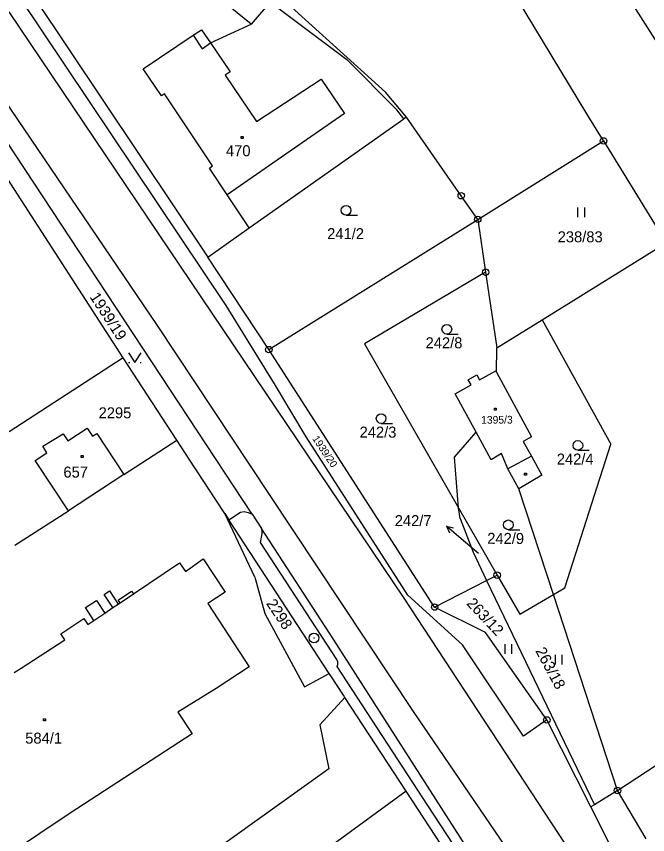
# Model space of a CAD drawing. Extents: x -795483 to -789093, y -1112258 to -1108741.
# Drawn here: x -791519.7 to -791422.1, y -1111421 to -1111294.6 of the extents above; entities that cross this region are included whole.
import ezdxf

# ---------------------------------------------------------------- set-up
doc = ezdxf.new("R2010")
doc.units = 0
for name, color, linetype in [('Komunikace', 7, 'Continuous'), ('Vrstva 1', 7, 'Continuous'), ('Vrstva 14', 7, 'Continuous'), ('Vrstva 15', 7, 'Continuous'), ('Vrstva 16', 7, 'Continuous'), ('Vrstva 2', 7, 'Continuous'), ('Vrstva 23', 7, 'Continuous'), ('Vrstva 25', 7, 'Continuous'), ('Vrstva 28', 7, 'Continuous')]:
    doc.layers.add(name, color=color, linetype=linetype)

msp = doc.modelspace()

# ---------------------------------------------------------------- linework, layer by layer
at = {"layer": 'Komunikace'}
msp.add_line((-791448.27, -1111377.57), (-791450.94, -1111375.27), dxfattribs=at)
at = {"layer": 'Vrstva 1'}
for p, q in [((-791453.88, -1111246.33), (-791418.6, -1111301.97)), ((-791431.53, -1111309.64), (-791464.81, -1111254.53)), ((-791462.64, -1111306.28), (-791491.11, -1111280.51)), ((-791485.12, -1111288.85), (-791468.64, -1111301.26)), ((-791487.25, -1111339.25), (-791519.47, -1111291.13)), ((-791517.06, -1111291.49), (-791490.12, -1111331.77)), ((-791483.4, -1111295.77), (-791487.72, -1111292.28)), ((-791489.68, -1111298.68), (-791483.4, -1111295.77)), ((-791492.38, -1111297.5), (-791491.07, -1111296.63)), ((-791491.07, -1111296.63), (-791489.68, -1111298.68)), ((-791500.07, -1111302.68), (-791492.38, -1111297.5)), ((-791460.91, -1111309.02), (-791468.64, -1111301.26)), ((-791497.27, -1111306.87), (-791500.07, -1111302.68)), ((-791496.79, -1111306.55), (-791497.27, -1111306.87)), ((-791489.38, -1111317.68), (-791496.79, -1111306.55)), ((-791459.41, -1111310.14), (-791462.64, -1111306.28)), ((-791459.8, -1111310.42), (-791460.91, -1111309.02)), ((-791428.96, -1111313.82), (-791431.53, -1111309.64)), ((-791483.25, -1111371.46), (-791523.47, -1111310.45)), ((-791483.7, -1111327.25), (-791459.8, -1111310.42)), ((-791459.41, -1111310.14), (-791459.8, -1111310.42)), ((-791450.94, -1111322.28), (-791459.41, -1111310.14)), ((-791503.19, -1111347.33), (-791525.98, -1111312.06)), ((-791448.39, -1111325.93), (-791428.96, -1111313.82)), ((-791428.96, -1111313.82), (-791419.28, -1111329.58)), ((-791489.86, -1111318.01), (-791489.38, -1111317.68)), ((-791487.12, -1111322.12), (-791489.86, -1111318.01)), ((-791483.7, -1111327.25), (-791487.12, -1111322.12)), ((-791448.39, -1111325.93), (-791450.94, -1111322.28)), ((-791480.67, -1111346.05), (-791448.39, -1111325.93)), ((-791448.39, -1111325.93), (-791447.17, -1111334.08)), ((-791490.12, -1111331.77), (-791483.7, -1111327.25)), ((-791438.46, -1111341.46), (-791419.28, -1111329.58)), ((-791480.67, -1111346.05), (-791490.12, -1111331.77)), ((-791447.17, -1111334.08), (-791465.91, -1111345.17)), ((-791447.17, -1111334.08), (-791445.43, -1111345.78)), ((-791479.79, -1111351.35), (-791487.25, -1111339.25)), ((-791445.43, -1111345.78), (-791438.46, -1111341.46)), ((-791438.46, -1111341.46), (-791427.83, -1111360.65)), ((-791465.91, -1111345.17), (-791451.38, -1111370.48)), ((-791455.05, -1111385.82), (-791480.67, -1111346.05)), ((-791445.49, -1111349.56), (-791445.43, -1111345.78)), ((-791503.19, -1111347.33), (-791520.8, -1111358.76)), ((-791494.9, -1111360.04), (-791503.19, -1111347.33)), ((-791449.87, -1111350.7), (-791448.55, -1111349.95)), ((-791448.55, -1111349.95), (-791448.1, -1111350.74)), ((-791448.1, -1111350.74), (-791445.62, -1111349.31)), ((-791445.62, -1111349.31), (-791445.49, -1111349.56)), ((-791445.49, -1111349.56), (-791440.1, -1111359.51)), ((-791474.9, -1111359.54), (-791479.79, -1111351.35)), ((-791451.86, -1111352.9), (-791449.41, -1111351.49)), ((-791449.41, -1111351.49), (-791449.87, -1111350.7)), ((-791448.65, -1111358.79), (-791451.86, -1111352.9)), ((-791515.62, -1111360.96), (-791512.44, -1111359.07)), ((-791512.44, -1111359.07), (-791511.72, -1111360.12)), ((-791511.72, -1111360.12), (-791508.76, -1111358.18)), ((-791508.76, -1111358.18), (-791507.94, -1111359.42)), ((-791507.94, -1111359.42), (-791507.25, -1111359)), ((-791507.25, -1111359), (-791503.09, -1111365.32)), ((-791451.96, -1111362.65), (-791448.65, -1111358.79)), ((-791446.3, -1111363.09), (-791448.65, -1111358.79)), ((-791503.09, -1111365.32), (-791494.9, -1111360.04)), ((-791492.9, -1111363.12), (-791494.9, -1111360.04)), ((-791459.18, -1111383.97), (-791474.9, -1111359.54)), ((-791440.1, -1111359.51), (-791441.36, -1111360.24)), ((-791441.36, -1111360.24), (-791440.11, -1111362.5)), ((-791514.96, -1111361.99), (-791515.62, -1111360.96)), ((-791434.95, -1111382.84), (-791427.83, -1111360.65)), ((-791516.77, -1111363.18), (-791514.96, -1111361.99)), ((-791451.38, -1111370.48), (-791451.96, -1111362.65)), ((-791444.73, -1111362.11), (-791446.3, -1111363.09)), ((-791443.73, -1111364.47), (-791444.73, -1111362.11)), ((-791440.11, -1111362.5), (-791438.5, -1111365.44)), ((-791513.95, -1111367.47), (-791516.77, -1111363.18)), ((-791492.12, -1111364.31), (-791492.9, -1111363.12)), ((-791490.53, -1111366.74), (-791492.12, -1111364.31)), ((-791503.09, -1111365.32), (-791511.65, -1111370.96)), ((-791442.05, -1111367.55), (-791443.73, -1111364.47)), ((-791438.5, -1111365.44), (-791442.05, -1111367.55)), ((-791490.17, -1111367.3), (-791490.53, -1111366.74)), ((-791511.65, -1111370.96), (-791513.95, -1111367.47)), ((-791487.5, -1111371.37), (-791490.17, -1111367.3)), ((-791436.71, -1111383.88), (-791442.05, -1111367.55)), ((-791451.1, -1111372.14), (-791451.38, -1111370.48)), ((-791451.38, -1111370.48), (-791445.4, -1111380.89)), ((-791519.91, -1111376.27), (-791511.65, -1111370.96)), ((-791487.5, -1111371.37), (-791486.87, -1111372.34)), ((-791482.82, -1111381.18), (-791487.5, -1111371.37)), ((-791486.87, -1111372.34), (-791485.05, -1111371.15)), ((-791485.05, -1111371.15), (-791484.49, -1111371.04)), ((-791484.49, -1111371.04), (-791483.85, -1111371.22)), ((-791483.85, -1111371.22), (-791483.25, -1111371.46)), ((-791483.25, -1111371.46), (-791481.8, -1111373.68)), ((-791471.35, -1111396.06), (-791486.87, -1111372.34)), ((-791451.1, -1111372.14), (-791449.11, -1111377.36)), ((-791470.64, -1111390.91), (-791481.8, -1111373.68)), ((-791481.73, -1111374.12), (-791481.8, -1111373.68)), ((-791481.72, -1111374.51), (-791481.73, -1111374.12)), ((-791481.96, -1111375.86), (-791481.72, -1111374.51)), ((-791470.15, -1111393.91), (-791481.96, -1111375.86)), ((-791449.11, -1111377.36), (-791447.02, -1111381.72)), ((-791501.61, -1111383.79), (-791494.49, -1111379.01)), ((-791494.49, -1111379.01), (-791493.55, -1111380.32)), ((-791493.55, -1111380.32), (-791490.83, -1111378.37)), ((-791490.83, -1111378.37), (-791487.43, -1111383.54)), ((-791482.82, -1111381.18), (-791481.29, -1111386.81)), ((-791455.05, -1111385.82), (-791447.02, -1111381.72)), ((-791447.02, -1111381.72), (-791445.4, -1111380.89)), ((-791447.02, -1111381.72), (-791430.36, -1111416.35)), ((-791445.4, -1111380.89), (-791441.88, -1111386.93)), ((-791436.71, -1111383.88), (-791434.95, -1111382.84)), ((-791506.14, -1111383.86), (-791505.32, -1111383.33)), ((-791504.76, -1111385.9), (-791506.14, -1111383.86)), ((-791505.32, -1111383.33), (-791503.95, -1111385.36)), ((-791503.97, -1111384.74), (-791501.91, -1111383.37)), ((-791501.91, -1111383.37), (-791501.61, -1111383.79)), ((-791487.43, -1111383.54), (-791490.1, -1111385.29)), ((-791450.73, -1111391.68), (-791459.18, -1111383.97)), ((-791441.88, -1111386.93), (-791436.71, -1111383.88)), ((-791426.8, -1111414.15), (-791436.71, -1111383.88)), ((-791508.98, -1111385.91), (-791507.33, -1111384.79)), ((-791507.33, -1111384.79), (-791506.04, -1111386.76)), ((-791503.66, -1111385.16), (-791503.97, -1111384.74)), ((-791503.95, -1111385.36), (-791503.66, -1111385.16)), ((-791490.1, -1111385.29), (-791483.72, -1111395.04)), ((-791447.2, -1111389.76), (-791455.05, -1111385.82)), ((-791507.71, -1111387.88), (-791508.98, -1111385.91)), ((-791506.04, -1111386.76), (-791504.76, -1111385.9)), ((-791481.29, -1111386.81), (-791475.14, -1111398.16)), ((-791512.8, -1111389.98), (-791509.24, -1111387.58)), ((-791509.24, -1111387.58), (-791508.63, -1111388.5)), ((-791508.63, -1111388.5), (-791507.71, -1111387.88)), ((-791426.8, -1111414.15), (-791386.85, -1111387.87)), ((-791518.97, -1111395.24), (-791512.19, -1111390.89)), ((-791512.19, -1111390.89), (-791512.8, -1111389.98)), ((-791437.72, -1111403.26), (-791447.2, -1111389.76)), ((-791444.18, -1111432.13), (-791470.64, -1111390.91)), ((-791441.33, -1111405.78), (-791450.73, -1111391.68)), ((-791469.99, -1111394.3), (-791470.15, -1111393.91)), ((-791470, -1111394.72), (-791469.99, -1111394.3)), ((-791520.04, -1111395.92), (-791518.97, -1111395.24)), ((-791483.72, -1111395.04), (-791488.81, -1111398.41)), ((-791470.13, -1111395.02), (-791470, -1111394.72)), ((-791456.09, -1111416.47), (-791470.13, -1111395.02)), ((-791475.14, -1111398.16), (-791471.35, -1111396.06)), ((-791471.1, -1111396.44), (-791471.35, -1111396.06)), ((-791469.13, -1111399.45), (-791471.1, -1111396.44)), ((-791488.81, -1111398.41), (-791494.75, -1111402.04)), ((-791468.92, -1111399.78), (-791469.13, -1111399.45)), ((-791468.92, -1111399.78), (-791472.8, -1111404)), ((-791459.46, -1111414.24), (-791468.92, -1111399.78)), ((-791494.75, -1111402.04), (-791492.54, -1111405.41)), ((-791437.72, -1111403.26), (-791441.33, -1111405.78)), ((-791430.93, -1111416.7), (-791437.72, -1111403.26)), ((-791472.8, -1111404), (-791471.42, -1111410.81)), ((-791492.54, -1111405.41), (-791511.39, -1111417.68)), ((-791471.42, -1111410.81), (-791498.05, -1111429.86)), ((-791459.46, -1111414.24), (-791470.74, -1111422.48)), ((-791446.66, -1111433.82), (-791459.46, -1111414.24)), ((-791426.8, -1111414.15), (-791430.36, -1111416.35)), ((-791422.35, -1111421.64), (-791426.8, -1111414.15)), ((-791438.2, -1111443.78), (-791456.09, -1111416.47)), ((-791430.36, -1111416.35), (-791430.93, -1111416.7)), ((-791420.68, -1111436.99), (-791430.93, -1111416.7)), ((-791511.39, -1111417.68), (-791535.58, -1111433.83))]:
    msp.add_line(p, q, dxfattribs=at)
at = {"layer": 'Vrstva 16'}
for p, q in [((-791450.94, -1111375.27), (-791453.22, -1111373.31)), ((-791453.22, -1111373.31), (-791452.78, -1111374.35)), ((-791453.22, -1111373.31), (-791452.13, -1111373.59))]:
    msp.add_line(p, q, dxfattribs=at)
at = {"layer": 'Vrstva 2'}
for p, q in [((-791480.88, -1111292.85), (-791483.4, -1111295.77)), ((-791459.74, -1111384.47), (-791520.79, -1111293.88)), ((-791492.38, -1111297.5), (-791490.98, -1111299.57)), ((-791490.98, -1111299.57), (-791489.68, -1111298.68)), ((-791489.68, -1111298.68), (-791486.67, -1111303.14)), ((-791486.67, -1111303.14), (-791487.4, -1111303.64)), ((-791487.4, -1111303.64), (-791482.56, -1111310.8)), ((-791482.56, -1111310.8), (-791472.59, -1111304.28)), ((-791472.59, -1111304.28), (-791468.99, -1111309.57)), ((-791521.57, -1111307.48), (-791497.91, -1111342.32)), ((-791468.99, -1111309.57), (-791487.12, -1111322.12)), ((-791497.91, -1111342.32), (-791480.62, -1111368.45)), ((-791440.11, -1111362.5), (-791443.73, -1111364.47)), ((-791480.62, -1111368.45), (-791458.38, -1111401.94)), ((-791503.66, -1111385.16), (-791501.61, -1111383.79)), ((-791426.86, -1111434.61), (-791459.74, -1111384.47)), ((-791504.76, -1111385.9), (-791503.95, -1111385.36)), ((-791507.71, -1111387.88), (-791506.04, -1111386.76)), ((-791458.38, -1111401.94), (-791432.7, -1111439.51))]:
    msp.add_line(p, q, dxfattribs=at)
at = {"layer": 'Vrstva 23'}
for p, q in [((-791432.91, -1111325.61), (-791432.91, -1111324.11)), ((-791431.91, -1111324.11), (-791431.91, -1111325.61)), ((-791468.73, -1111325.29), (-791466.98, -1111325.29)), ((-791453.17, -1111343.65), (-791451.42, -1111343.65)), ((-791502.38, -1111346.56), (-791501.38, -1111348.06)), ((-791502.38, -1111346.56), (-791501.38, -1111348.06)), ((-791501.38, -1111348.06), (-791500.38, -1111346.56)), ((-791501.38, -1111348.06), (-791500.38, -1111346.56)), ((-791502.38, -1111348.06), (-791502.18, -1111348.06)), ((-791502.38, -1111348.06), (-791502.18, -1111348.06)), ((-791500.58, -1111348.06), (-791500.38, -1111348.06)), ((-791500.58, -1111348.06), (-791500.38, -1111348.06)), ((-791463.32, -1111357.45), (-791461.57, -1111357.45)), ((-791432.92, -1111361.61), (-791431.17, -1111361.61)), ((-791443.66, -1111373.87), (-791441.91, -1111373.87)), ((-791444.18, -1111393.03), (-791444.18, -1111391.53)), ((-791443.18, -1111391.53), (-791443.18, -1111393.03)), ((-791436.39, -1111394.71), (-791436.39, -1111393.21)), ((-791435.39, -1111393.21), (-791435.39, -1111394.71))]:
    msp.add_line(p, q, dxfattribs=at)
for centre in [(-791468.73, -1111324.54), (-791453.17, -1111342.9), (-791463.32, -1111356.7), (-791432.92, -1111360.86), (-791443.66, -1111373.12)]:
    msp.add_circle(centre, 0.75, dxfattribs=at)
at = {"layer": 'Vrstva 25'}
for p, q in [((-791484.96, -1111313.13), (-791484.66, -1111313.13)), ((-791484.96, -1111313.43), (-791484.96, -1111313.13)), ((-791484.66, -1111313.43), (-791484.96, -1111313.43)), ((-791484.66, -1111313.13), (-791484.66, -1111313.43)), ((-791445.82, -1111355.1), (-791445.52, -1111355.1)), ((-791445.82, -1111355.4), (-791445.82, -1111355.1)), ((-791445.52, -1111355.4), (-791445.82, -1111355.4)), ((-791445.52, -1111355.1), (-791445.52, -1111355.4)), ((-791509.69, -1111362.4), (-791509.39, -1111362.4)), ((-791509.69, -1111362.7), (-791509.69, -1111362.4)), ((-791509.39, -1111362.7), (-791509.69, -1111362.7)), ((-791509.39, -1111362.4), (-791509.39, -1111362.7)), ((-791441.18, -1111365.13), (-791440.88, -1111365.13)), ((-791441.18, -1111365.43), (-791441.18, -1111365.13)), ((-791440.88, -1111365.43), (-791441.18, -1111365.43)), ((-791440.88, -1111365.13), (-791440.88, -1111365.43)), ((-791515.5, -1111403.11), (-791515.2, -1111403.11)), ((-791515.5, -1111403.41), (-791515.5, -1111403.11)), ((-791515.2, -1111403.41), (-791515.5, -1111403.41)), ((-791515.2, -1111403.11), (-791515.2, -1111403.41))]:
    msp.add_line(p, q, dxfattribs=at)
at = {"layer": 'Vrstva 28'}
for centre, radius in [((-791428.96, -1111313.82), 0.5), ((-791428.96, -1111313.82), 0.01), ((-791450.94, -1111322.28), 0.5), ((-791450.94, -1111322.28), 0.01), ((-791448.39, -1111325.93), 0.5), ((-791448.39, -1111325.93), 0.01), ((-791447.17, -1111334.08), 0.5), ((-791447.17, -1111334.08), 0.01), ((-791480.67, -1111346.05), 0.5), ((-791480.67, -1111346.05), 0.01), ((-791445.4, -1111380.89), 0.5), ((-791445.4, -1111380.89), 0.01), ((-791455.05, -1111385.82), 0.5), ((-791455.05, -1111385.82), 0.01), ((-791473.7, -1111390.6), 0.75), ((-791473.7, -1111390.6), 0.01), ((-791437.72, -1111403.26), 0.5), ((-791437.72, -1111403.26), 0.01), ((-791426.8, -1111414.15), 0.5), ((-791426.8, -1111414.15), 0.01)]:
    msp.add_circle(centre, radius, dxfattribs=at)

# ---------------------------------------------------------------- texts
at = {"layer": 'Vrstva 14'}
for s, height, p in [('241/2', 1.7, (-791471.66, -1111328.99)), ('238/83', 1.7, (-791436.04, -1111329.48)), ('242/8', 1.7, (-791456.45, -1111345.85)), ('2295', 1.7, (-791506.98, -1111356.67)), ('242/3', 1.7, (-791466.65, -1111359.65)), ('242/4', 1.7, (-791436.18, -1111363.81)), ('242/7', 0.1, (-791448.27, -1111377.57))]:
    msp.add_text(s, height=height, dxfattribs=at).set_placement(p)
for s, height, rotation, p in [('1939/19', 1.7, 302.889, (-791508.42, -1111337.9)), ('1939/20', 1.14, 303.8144, (-791474.01, -1111359.81)), ('242/9', 1.7, 359.677, (-791446.93, -1111376.05)), ('2298', 1.7, 303.6857, (-791481.14, -1111385.27)), ('263/12', 1.7, 313.2599, (-791450.23, -1111385.35)), ('263/18', 1.7, 298.1913, (-791439.53, -1111392.58))]:
    msp.add_text(s, height=height, rotation=rotation, dxfattribs=at).set_placement(p)
at = {"layer": 'Vrstva 15'}
for s, p in [('470', (-791487.3, -1111316.18)), ('657', (-791512.42, -1111365.82)), ('584/1', (-791518.32, -1111406.92))]:
    msp.add_text(s, height=1.7, dxfattribs=at).set_placement(p)
msp.add_text('1395/3', height=1.19, rotation=0.3172, dxfattribs=at).set_placement((-791447.86, -1111357.5))
at = {"layer": 'Vrstva 16'}
msp.add_text('242/7', height=1.7, dxfattribs=at).set_placement((-791461.22, -1111373.32))

doc.saveas('drawing.dxf')
